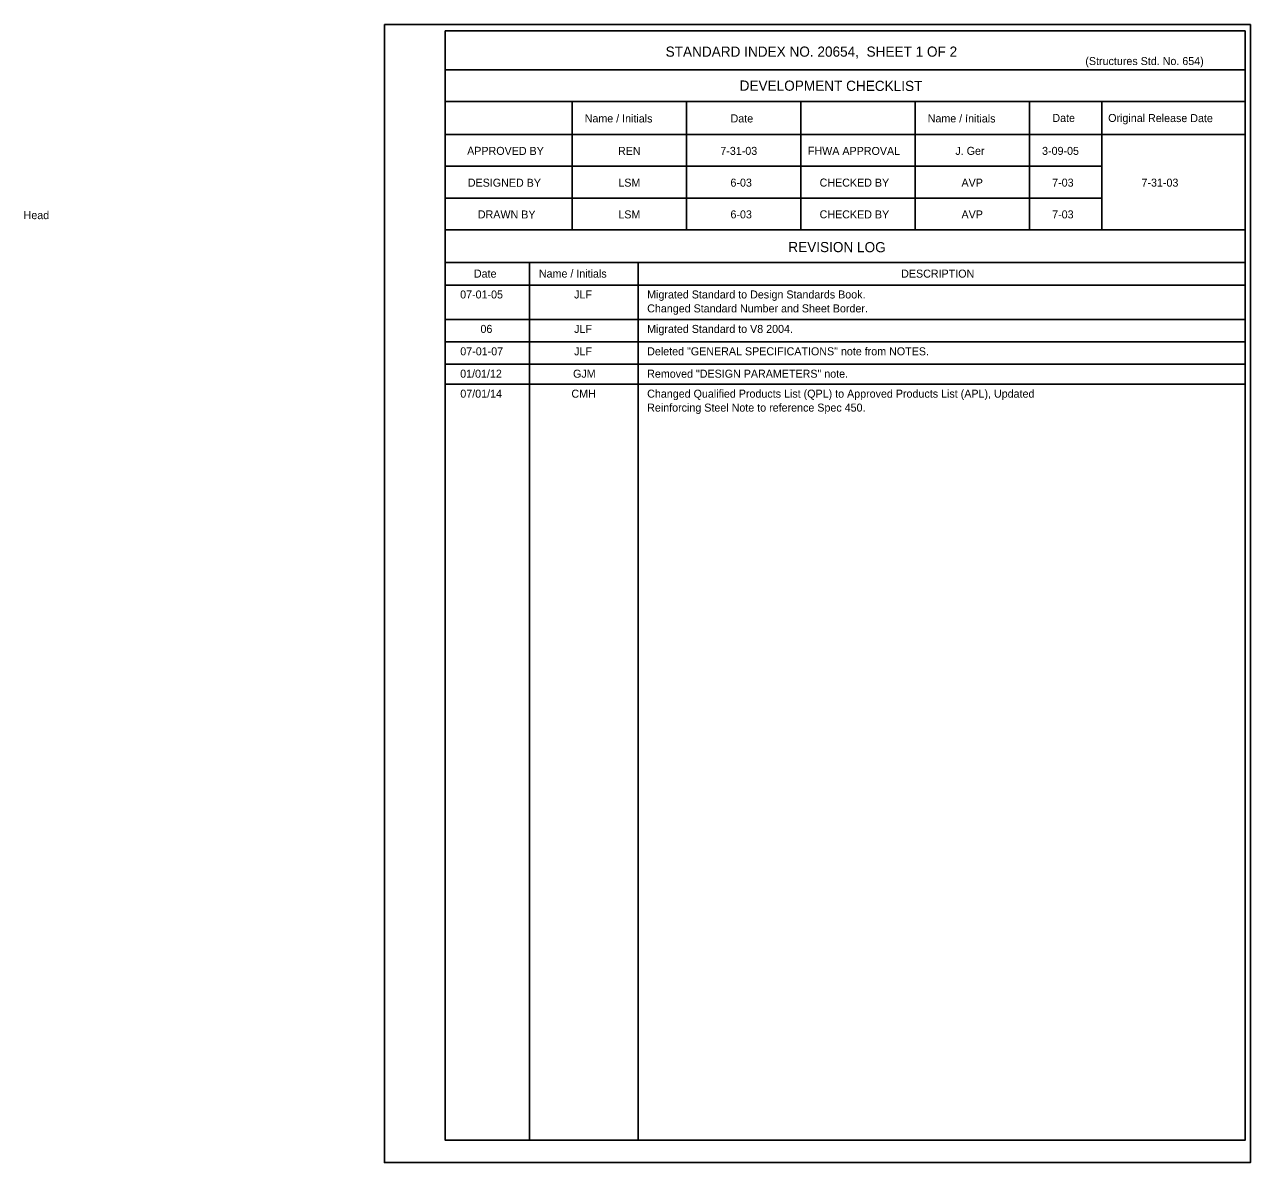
# Model space of a CAD drawing. Extents: x 120519.5 to 120592, y 120568.7 to 120603.1.
# Drawn here: x 120561.13 to 120592.01, y 120568.69 to 120597.36 of the extents above; entities that cross this region are included whole.
import ezdxf

# ---------------------------------------------------------------- set-up
doc = ezdxf.new("R2010")
doc.units = 0
for name, color, linetype in [('Border', 7, 'Continuous'), ('Dimension', 7, 'Continuous'), ('PlotBorder_dp', 7, 'Continuous'), ('TextStructures', 7, 'Continuous')]:
    doc.layers.add(name, color=color, linetype=linetype)

msp = doc.modelspace()

# ---------------------------------------------------------------- linework, layer by layer
at = {"layer": 'Border'}
for p, q in [((120591.874, 120596.217), (120571.727, 120596.217)), ((120591.874, 120595.417), (120571.727, 120595.417)), ((120574.927, 120595.417), (120574.927, 120592.189)), ((120577.807, 120595.417), (120577.807, 120592.189)), ((120580.687, 120595.417), (120580.687, 120592.189)), ((120583.567, 120595.417), (120583.567, 120592.189)), ((120586.447, 120595.417), (120586.447, 120592.189)), ((120588.262, 120595.417), (120588.262, 120592.189)), ((120591.874, 120594.589), (120571.727, 120594.589)), ((120588.262, 120593.789), (120571.727, 120593.789)), ((120588.262, 120592.989), (120571.727, 120592.989)), ((120591.874, 120592.189), (120571.727, 120592.189)), ((120591.874, 120591.361), (120571.727, 120591.361)), ((120573.848, 120591.361), (120573.848, 120569.255)), ((120576.59, 120591.361), (120576.59, 120569.255)), ((120591.874, 120590.797), (120571.727, 120590.797))]:
    msp.add_line(p, q, dxfattribs=at)
msp.add_lwpolyline([(120571.728, 120597.197), (120591.874, 120597.197), (120591.874, 120569.255), (120571.728, 120569.255)], close=True, dxfattribs=at)
at = {"layer": 'Dimension'}
for p, q in [((120571.728, 120589.929), (120591.874, 120589.929)), ((120571.728, 120589.365), (120591.874, 120589.365)), ((120571.728, 120588.801), (120591.874, 120588.801)), ((120571.728, 120588.298), (120591.874, 120588.298))]:
    msp.add_line(p, q, dxfattribs=at)
at = {"layer": 'PlotBorder_dp'}
msp.add_line((120570.197, 120568.693), (120570.197, 120568.693), dxfattribs=at)
msp.add_lwpolyline([(120570.197, 120597.36), (120592.01, 120597.36), (120592.01, 120568.693), (120570.197, 120568.693)], close=True, dxfattribs=at)

# ---------------------------------------------------------------- texts
at = {"layer": 'TextStructures'}
for s, height, p in [('STANDARD INDEX NO. 20654,  SHEET 1 OF 2', 0.256, (120577.279, 120596.549)), ('(Structures Std. No. 654)', 0.2016, (120587.851, 120596.339)), ('REN', 0.2016, (120576.079, 120594.076)), ('7-31-03', 0.2016, (120578.657, 120594.076)), ('J. Ger', 0.2016, (120584.577, 120594.076)), ('3-09-05', 0.2016, (120586.761, 120594.076)), ('LSM', 0.2016, (120576.088, 120593.276)), ('6-03', 0.2016, (120578.912, 120593.276)), ('AVP', 0.2016, (120584.731, 120593.276)), ('7-03', 0.2016, (120587.015, 120593.276)), ('7-31-03', 0.2016, (120589.265, 120593.276)), ('Head', 0.2016, (120561.108, 120592.457)), ('LSM', 0.2016, (120576.088, 120592.476)), ('6-03', 0.2016, (120578.912, 120592.476)), ('AVP', 0.2016, (120584.731, 120592.476)), ('7-03', 0.2016, (120587.015, 120592.476)), ('DESCRIPTION', 0.2016, (120583.211, 120590.984)), ('07-01-05', 0.2016, (120572.103, 120590.459)), ('JLF', 0.2016, (120574.974, 120590.459)), ('Migrated Standard to Design Standards Book.', 0.2016, (120576.814, 120590.459)), ('Changed Standard Number and Sheet Border.', 0.2016, (120576.814, 120590.108)), ('06', 0.2016, (120572.615, 120589.591)), ('JLF', 0.2016, (120574.974, 120589.591)), ('Migrated Standard to V8 2004.', 0.2016, (120576.814, 120589.591)), ('07-01-07', 0.2016, (120572.107, 120589.027)), ('JLF', 0.2016, (120574.974, 120589.027)), ('Deleted "GENERAL SPECIFICATIONS" note from NOTES.', 0.2016, (120576.814, 120589.027)), ('01/01/12', 0.2016, (120572.104, 120588.463)), ('GJM', 0.2016, (120574.947, 120588.463)), ('Removed "DESIGN PARAMETERS" note.', 0.2016, (120576.814, 120588.463)), ('07/01/14', 0.2016, (120572.108, 120587.96)), ('CMH', 0.2016, (120574.906, 120587.96)), ('Changed Qualified Products List (QPL) to Approved Products List (APL), Updated', 0.2016, (120576.814, 120587.96)), ('Reinforcing Steel Note to reference Spec 450.', 0.2016, (120576.814, 120587.609))]:
    msp.add_text(s, height=height, dxfattribs=at).set_placement(p)
for s, height, p in [('DEVELOPMENT CHECKLIST', 0.256, (120579.143, 120595.694)), ('Name / Initials', 0.2016, (120575.24, 120594.896)), ('Date', 0.2016, (120578.915, 120594.894)), ('Name / Initials', 0.2016, (120583.88, 120594.896)), ('Date', 0.2016, (120587.02, 120594.906)), ('Original Release Date', 0.2016, (120588.426, 120594.906)), ('APPROVED BY', 0.2016, (120572.279, 120594.078)), ('FHWA APPROVAL', 0.2016, (120580.863, 120594.078)), ('DESIGNED BY', 0.2016, (120572.296, 120593.276)), ('CHECKED BY', 0.2016, (120581.157, 120593.278)), ('DRAWN BY', 0.2016, (120572.549, 120592.476)), ('CHECKED BY', 0.2016, (120581.157, 120592.478)), ('REVISION LOG', 0.256, (120580.369, 120591.628)), ('Date', 0.2016, (120572.45, 120590.985)), ('Name / Initials', 0.2016, (120574.086, 120590.987))]:
    msp.add_text(s, height=height, rotation=359.8756, dxfattribs=at).set_placement(p)

doc.saveas('drawing.dxf')
